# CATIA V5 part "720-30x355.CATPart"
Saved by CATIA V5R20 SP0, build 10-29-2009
Part number: 720-30x355
Definition: NONE
Nomenclature: 720-30x355
Source: Unknown
Description: 720-30x355
Bounding box of the stored display mesh (mm): x 0 to 355, y -15 to 15, z -15 to 15
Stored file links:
  C:\Users\Utente\Desktop\IO LAVORO\3D X SITO CF\X SITO\720\720-30x355.CATPart

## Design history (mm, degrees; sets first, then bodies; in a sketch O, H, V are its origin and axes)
Body1 "720-30x355" (main body)
  Solid1: solid without history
